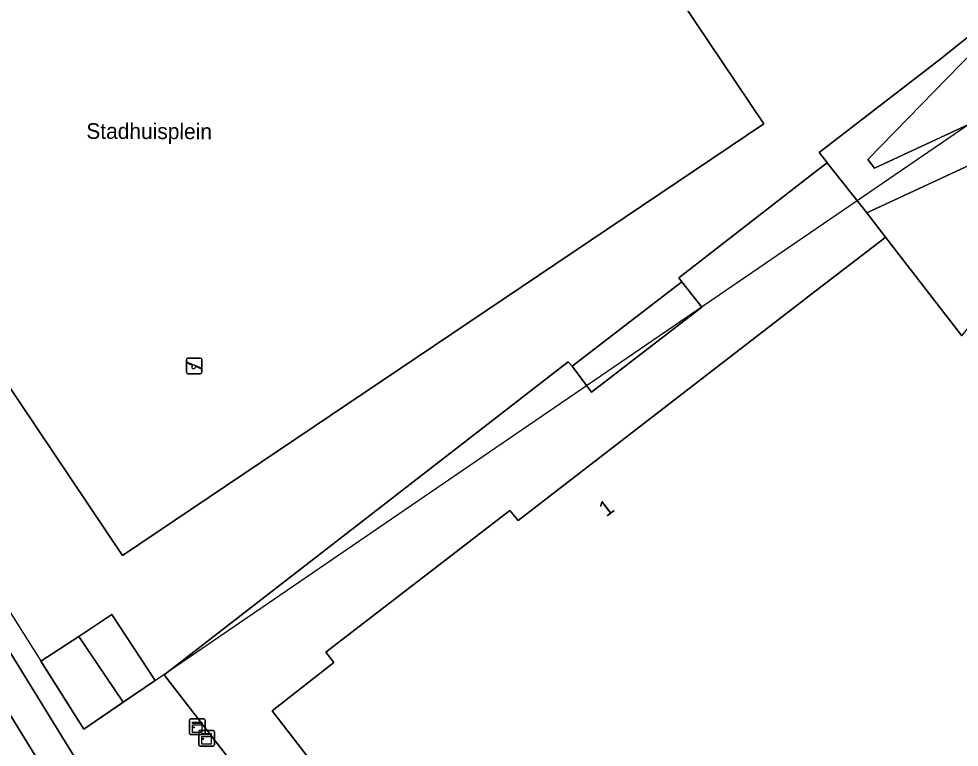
# Model space of a CAD drawing. Extents: x 161087 to 161926, y 382572 to 383873.
# Drawn here: x 161449.1 to 161509.1, y 382884.6 to 382931.1 of the extents above; entities that cross this region are included whole.
import ezdxf

# ---------------------------------------------------------------- set-up
doc = ezdxf.new("R2010")
doc.units = 0
for name, color, linetype in [('IMGEO_Berm_open', 7, 'Continuous'), ('IMGEO_Fietspad_gesloten', 7, 'Continuous'), ('IMGEO_Groenvoorziening', 7, 'Continuous'), ('IMGEO_Kast', 7, 'Continuous'), ('IMGEO_Openbare_ruimte_label', 7, 'Continuous'), ('IMGEO_Pand', 7, 'Continuous'), ('IMGEO_Pand_nummerreeks', 7, 'Continuous'), ('IMGEO_Pand_overbouw', 7, 'Continuous'), ('IMGEO_Speelvoorziening', 7, 'Continuous'), ('IMGEO_Voetgangersgebied_open', 7, 'Continuous'), ('IMGEO_Voetpad_op_trap', 7, 'Continuous')]:
    doc.layers.add(name, color=color, linetype=linetype)

msp = doc.modelspace()

# ---------------------------------------------------------------- linework, layer by layer
at = {"layer": 'IMGEO_Berm_open'}
msp.add_lwpolyline([(161470.317, 382851.298), (161467.37, 382855.98), (161433.209, 382911.46)], dxfattribs=at)
at = {"layer": 'IMGEO_Fietspad_gesloten'}
for points in [[(161476.379, 382845.501), (161473.209, 382850.496), (161469.267, 382856.908), (161434.891, 382912.704), (161425.738, 382927.535), (161423.001, 382931.728), (161421.785, 382933.513), (161421.709, 382933.625), (161420.782, 382934.985), (161418.673, 382937.998), (161418.424, 382938.34), (161418.173, 382938.68), (161416.013, 382941.491), (161413.737, 382944.446), (161413.383, 382944.906), (161412.674, 382945.831), (161395.778, 382967.851), (161371.138, 383000)], [(161423.738, 382926.662), (161428.393, 382919.248), (161433.209, 382911.46), (161467.37, 382855.98), (161470.317, 382851.298)]]:
    msp.add_lwpolyline(points, dxfattribs=at)
at = {"layer": 'IMGEO_Groenvoorziening'}
for points in [[(161520.273, 382929.257), (161519.611, 382930.139), (161518.49, 382931.632), (161516.557, 382934.206), (161510.935, 382929.942), (161503.293, 382922.112), (161503.727, 382921.558)], [(161503.226, 382918.699), (161504.422, 382917.152), (161509.299, 382910.845), (161522.233, 382926.745), (161521.802, 382927.331)]]:
    msp.add_lwpolyline(points, close=True, dxfattribs=at)
at = {"layer": 'IMGEO_Kast'}
for p, q in [((161459.95, 382885.461), (161459.95, 382886.302)), ((161459.95, 382886.302), (161459.95, 382885.461)), ((161460.025, 382886.386), (161460.866, 382886.386)), ((161460.866, 382886.386), (161460.025, 382886.386)), ((161460.95, 382886.311), (161460.95, 382885.47)), ((161460.95, 382885.47), (161460.95, 382886.311)), ((161460.875, 382885.386), (161460.034, 382885.386)), ((161460.034, 382885.386), (161460.875, 382885.386)), ((161460.548, 382884.729), (161460.548, 382885.57)), ((161460.548, 382885.57), (161460.548, 382884.729)), ((161460.623, 382885.654), (161461.464, 382885.654)), ((161461.464, 382885.654), (161460.623, 382885.654)), ((161461.548, 382885.579), (161461.548, 382884.738)), ((161461.548, 382884.738), (161461.548, 382885.579)), ((161461.473, 382884.654), (161460.632, 382884.654)), ((161460.632, 382884.654), (161461.473, 382884.654))]:
    msp.add_line(p, q, dxfattribs=at)
for points in [[(161460.145, 382886.176), (161460.745, 382886.176), (161460.745, 382886.091), (161460.145, 382886.091), (161460.145, 382886.176)], [(161460.145, 382886.001), (161460.745, 382886.001), (161460.745, 382885.512), (161460.145, 382885.512), (161460.145, 382886.001)], [(161460.743, 382885.444), (161461.343, 382885.444), (161461.343, 382885.359), (161460.743, 382885.359), (161460.743, 382885.444)], [(161460.743, 382885.269), (161461.343, 382885.269), (161461.343, 382884.78), (161460.743, 382884.78), (161460.743, 382885.269)]]:
    msp.add_lwpolyline(points, dxfattribs=at)
for centre in [(161460.229, 382885.85), (161460.827, 382885.118)]:
    msp.add_circle(centre, 0.0377, dxfattribs=at)
for centre, start, end in [((161460.028, 382886.308), 92.4484, 184.28452), ((161460.028, 382886.308), 92.4484, 184.28452), ((161460.872, 382886.308), 2.4484, 94.28452), ((161460.872, 382886.308), 2.4484, 94.28452), ((161460.028, 382885.464), 182.4484, 274.28452), ((161460.028, 382885.464), 182.4484, 274.28452), ((161460.626, 382885.576), 92.4484, 184.28452), ((161460.626, 382885.576), 92.4484, 184.28452), ((161460.872, 382885.464), 272.4484, 4.28452), ((161460.872, 382885.464), 272.4484, 4.28452), ((161461.47, 382885.576), 2.4484, 94.28452), ((161461.47, 382885.576), 2.4484, 94.28452), ((161460.626, 382884.732), 182.4484, 274.28452), ((161460.626, 382884.732), 182.4484, 274.28452), ((161461.47, 382884.732), 272.4484, 4.28452), ((161461.47, 382884.732), 272.4484, 4.28452)]:
    msp.add_arc(centre, 0.0779, start, end, dxfattribs=at)
at = {"layer": 'IMGEO_Pand'}
msp.add_lwpolyline([(161509.299, 382910.845), (161504.422, 382917.152), (161504.189, 382916.971), (161500, 382913.739), (161480.962, 382899.05), (161480.418, 382899.706), (161468.666, 382890.646), (161469.189, 382889.988), (161465.241, 382886.911), (161473.698, 382875.969), (161495.302, 382847.988), (161496.266, 382848.732), (161500, 382851.615), (161504.062, 382854.751), (161508.601, 382858.256), (161512.483, 382861.253)], dxfattribs=at)
msp.add_lwpolyline([(161452.886, 382891.657), (161450.47, 382890.077), (161453.212, 382885.739), (161455.716, 382887.451)], close=True, dxfattribs=at)
at = {"layer": 'IMGEO_Pand_overbouw'}
msp.add_lwpolyline([(161492.605, 382965.232), (161429.792, 382922.791), (161453.212, 382885.739), (161522.217, 382932.918), (161506.849, 382955.782), (161501.427, 382952.07)], close=True, dxfattribs=at)
at = {"layer": 'IMGEO_Speelvoorziening'}
for p, q in [((161459.76, 382908.536), (161459.76, 382909.336)), ((161459.76, 382909.336), (161459.76, 382908.536)), ((161459.86, 382909.436), (161460.65, 382909.436)), ((161460.65, 382909.436), (161459.86, 382909.436)), ((161460.75, 382909.336), (161460.75, 382908.536)), ((161460.75, 382908.536), (161460.75, 382909.336)), ((161460.143, 382908.964), (161459.804, 382909.101)), ((161459.829, 382909.161), (161460.705, 382908.808)), ((161460.681, 382908.748), (161460.341, 382908.885)), ((161460.65, 382908.436), (161459.86, 382908.436)), ((161459.86, 382908.436), (161460.65, 382908.436))]:
    msp.add_line(p, q, dxfattribs=at)
for centre, radius, start, end in [((161459.86, 382909.336), 0.1, 90, 180), ((161459.86, 382909.336), 0.1, 90, 180), ((161460.65, 382909.336), 0.1, 0, 90), ((161460.65, 382909.336), 0.1, 360, 90), ((161459.817, 382909.131), 0.0327, 68.07798, 248.07798), ((161460.222, 382908.874), 0.12, 130.99278, 5.16318), ((161460.693, 382908.778), 0.0327, 248.07798, 68.07798), ((161459.86, 382908.536), 0.1, 180, 270), ((161459.86, 382908.536), 0.1, 180, 270), ((161460.65, 382908.536), 0.1, 270, 0), ((161460.65, 382908.536), 0.1, 270, 0)]:
    msp.add_arc(centre, radius, start, end, dxfattribs=at)
at = {"layer": 'IMGEO_Voetgangersgebied_open'}
for points in [[(161491.048, 382965.377), (161486.36, 382972.355), (161487.398, 382973.001), (161487.593, 382973.143), (161489.566, 382970.234), (161491.831, 382971.755), (161492.041, 382971.904), (161494.312, 382973.384), (161494.555, 382973.544), (161494.8, 382973.709), (161487.535, 382984.276), (161418.673, 382937.998), (161420.782, 382934.985), (161421.709, 382933.625), (161421.785, 382933.513), (161423.001, 382931.728), (161425.738, 382927.535), (161434.891, 382912.704), (161469.267, 382856.908), (161473.209, 382850.496), (161476.379, 382845.501)], [(161464.634, 382881.042), (161458.339, 382889.209), (161484.144, 382909.195), (161484.399, 382908.913), (161491.418, 382914.303), (161491.228, 382914.562), (161500, 382921.365), (161500.704, 382921.911), (161500.61, 382922.031), (161500.185, 382922.554), (161507.902, 382928.506), (161510.463, 382930.552)], [(161473.698, 382875.969), (161465.241, 382886.911), (161469.189, 382889.988), (161468.666, 382890.646), (161480.418, 382899.706), (161480.962, 382899.05), (161500, 382913.739), (161504.189, 382916.971), (161504.422, 382917.152), (161503.226, 382918.699), (161500.704, 382921.911), (161500, 382921.365), (161491.228, 382914.562), (161491.418, 382914.303), (161492.692, 382912.683), (161485.65, 382907.256), (161484.399, 382908.913), (161484.144, 382909.195), (161458.339, 382889.209), (161464.634, 382881.042)]]:
    msp.add_lwpolyline(points, dxfattribs=at)
for points in [[(161469.152, 382965.318), (161428.165, 382937.798), (161455.681, 382896.825), (161496.661, 382924.391)], [(161496.661, 382924.391), (161455.681, 382896.825), (161428.165, 382937.798), (161469.152, 382965.318)], [(161457.766, 382888.83), (161455.716, 382887.451), (161453.212, 382885.739), (161450.47, 382890.077), (161452.886, 382891.657), (161454.998, 382893.052)], [(161454.998, 382893.052), (161452.886, 382891.657), (161455.716, 382887.451), (161457.766, 382888.83)]]:
    msp.add_lwpolyline(points, close=True, dxfattribs=at)
at = {"layer": 'IMGEO_Voetpad_op_trap'}
for points in [[(161510.463, 382930.552), (161507.902, 382928.506), (161500.185, 382922.554), (161500.61, 382922.031), (161500.704, 382921.911), (161503.226, 382918.699), (161521.802, 382927.331)], [(161520.273, 382929.257), (161503.727, 382921.558), (161503.293, 382922.112), (161510.935, 382929.942)]]:
    msp.add_lwpolyline(points, dxfattribs=at)
msp.add_lwpolyline([(161492.692, 382912.683), (161491.418, 382914.303), (161484.399, 382908.913), (161485.65, 382907.256)], close=True, dxfattribs=at)

# ---------------------------------------------------------------- texts
at = {"layer": 'IMGEO_Openbare_ruimte_label'}
msp.add_text('Stadhuisplein', height=1, rotation=359.77082, dxfattribs=at).set_placement((161453.365, 382923.439))
at = {"layer": 'IMGEO_Pand_nummerreeks'}
msp.add_text('1', height=1, rotation=37.66052, dxfattribs=at).set_placement((161486.592, 382899.247))

doc.saveas('drawing.dxf')
